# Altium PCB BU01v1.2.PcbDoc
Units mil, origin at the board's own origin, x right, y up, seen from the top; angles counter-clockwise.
Board outline 1015 x 695 mil, 2 copper layers (Top Layer, Bottom Layer); 7 components, 21 nets, 48 pads, 3 vias.
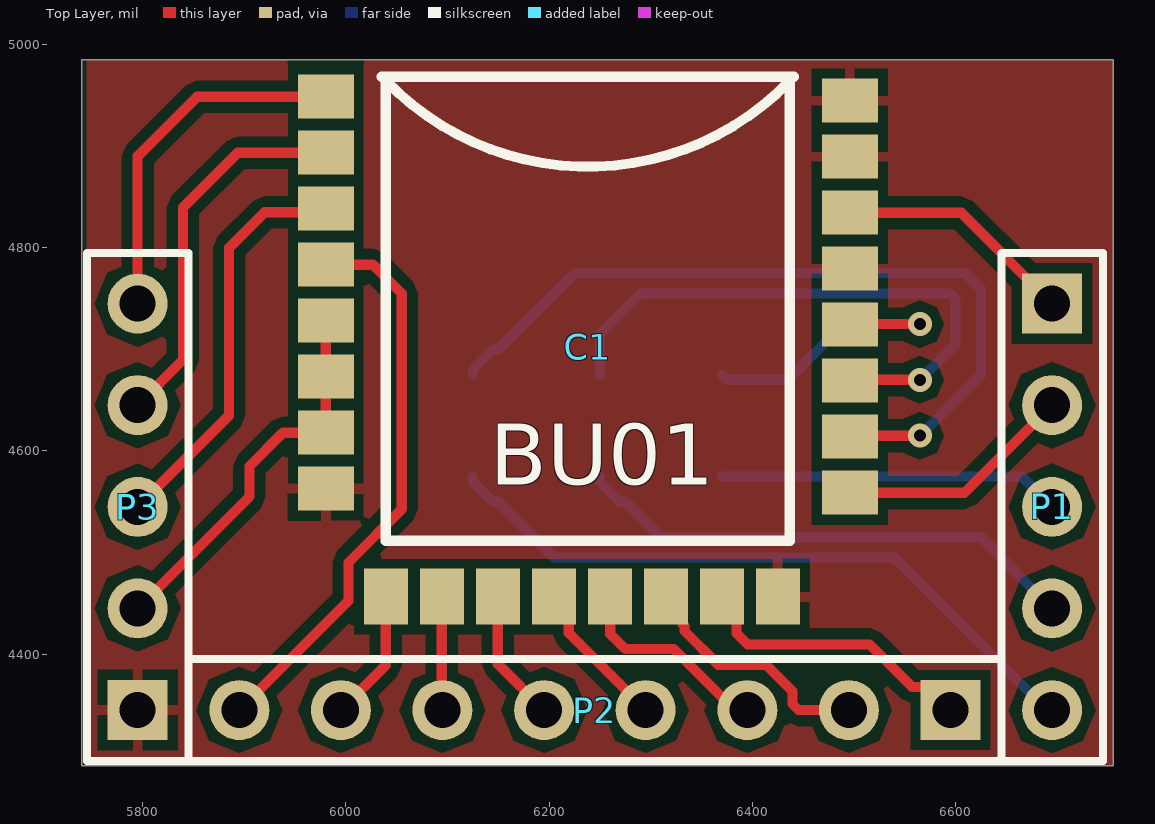
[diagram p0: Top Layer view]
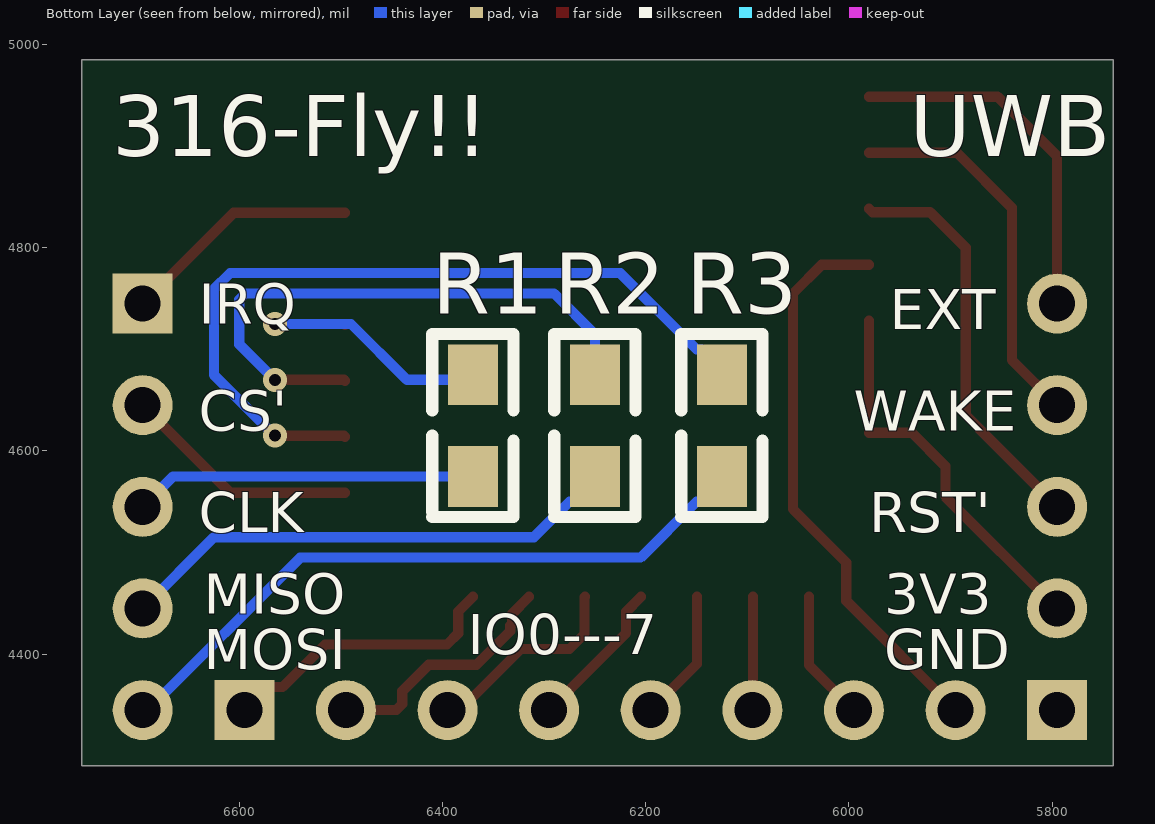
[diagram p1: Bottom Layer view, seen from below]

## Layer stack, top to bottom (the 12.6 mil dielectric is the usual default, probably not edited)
Top Solder: solder mask 0.4, Solder Resist, Dk 3.5
Top Layer: signal copper 1.4
Dielectric 1: dielectric 12.6, FR-4, Dk 4.8
Bottom Layer: signal copper 1.4
Bottom Solder: solder mask 0.4, Solder Resist, Dk 3.5

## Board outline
5740,4290 5740,4985 6755,4985 6755,4290

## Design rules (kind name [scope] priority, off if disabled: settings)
Clearance [All] p1: gap=10 ignorepadtopadclearanceinfootprint=FALSE except(0: Arc-Hole Track-Hole SMDPad-Hole THPad-Hole Via-Hole Fill-Hole Poly-Hole Region-Hole Text-Hole)
ComponentClearance [All] p1 off: gap=10 collisioncheckmode=3 verticalgap=10 showdistances=FALSE
PolygonConnect [All] p1: connectstyle=Relief reliefconductorwidth=10 reliefentries=4 polygonreliefangle="90 Angle" airgapwidth=10
RoutingVias [All] p1: holewidth=28 width=50 viastyle="Through Hole" minholewidth=28 minwidth=50 maxholewidth=28 maxwidth=50
SolderMaskExpansion [All] p1: expansion=4 istentingtop=FALSE
Width [All] p1: maxlimit=10 minlimit=10 preferedwidth=10
29 further rules are at their usual default settings.

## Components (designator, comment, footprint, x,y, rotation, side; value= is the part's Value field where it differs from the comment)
C1 "BU01" BU01 6240,4925 r0 top
P1 "Header 5" HDR1X5 6695,4745 r270 top
P2 "Header 8" HDR1X8 6595,4345 r180 top
P3 "Header 5" HDR1X5 5795,4345 r90 top
R1 "Res Semi" 0805 6370,4675 r270 bottom value=100
R2 "Res Semi" 0805 6250,4675 r270 bottom value=100
R3 "Res Semi" 0805 6125,4675 r270 bottom value=100

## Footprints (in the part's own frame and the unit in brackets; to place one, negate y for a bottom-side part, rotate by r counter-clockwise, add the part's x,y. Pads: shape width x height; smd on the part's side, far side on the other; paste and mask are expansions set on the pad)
0805 [mil]
  rect 60x49.21 smd: 1(0,0) 2(100,0)
  silkscreen extent -40,-40 140,40
BU01 [mm]
  rect 1.4x1.1 smd: 1(-6.6,0.6) 2(-6.6,-0.8) 3(-6.6,-2.2) 4(-6.6,-3.6) 5(-6.6,-5) 6(-6.6,-6.4) 7(-6.6,-7.8) 8(-6.6,-9.2) 17(6.5,-9.3) 18(6.5,-7.9) 19(6.5,-6.5) 20(6.5,-5.1) 21(6.5,-3.7) 22(6.5,-2.3) 23(6.5,-0.9) 24(6.5,0.5)
  rect 1.1x1.4 smd: 9(-5.1,-11.9) 10(-3.7,-11.9) 11(-2.3,-11.9) 12(-0.9,-11.9) 13(0.5,-11.9) 14(1.9,-11.9) 15(3.3,-11.9) 16(4.7,-11.9)
  silkscreen extent -5.2,-10.5 5.1,1.1
HDR1X5 [mm] "Connector; Header; 5 Position"
  rect 1.5x1.5 hole 0.9: 1(0,0)
  round 1.5 hole 0.9: 2(2.54,0) 3(5.08,0) 4(7.62,0) 5(10.16,0)
  silkscreen extent -1.27,-1.27 11.43,1.27
HDR1X8 [mm] "Connector; Header; 8 Position"
  rect 1.5x1.5 hole 0.9: 1(0,0)
  round 1.5 hole 0.9: 2(2.54,0) 3(5.08,0) 4(7.62,0) 5(10.16,0) 6(12.7,0) 7(15.24,0) 8(17.78,0)
  silkscreen extent -1.27,-1.27 19.05,1.27

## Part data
P1 P3: "Header, 5-Pin"
P2: "Header, 8-Pin"
R1 R2 R3: "Semiconductor Resistor"

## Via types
v1: diameter 23.62, hole 11.81, Top Layer to Bottom Layer, 3 vias

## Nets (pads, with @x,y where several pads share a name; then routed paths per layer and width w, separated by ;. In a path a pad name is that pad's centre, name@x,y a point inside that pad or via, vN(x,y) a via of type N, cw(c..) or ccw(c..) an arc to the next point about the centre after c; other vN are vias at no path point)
3V3: C1.5 C1.6 C1.7 P3.2 | length 384.6
  Top Layer w10: P3.2 5905,4555 5905,4585 5937.91,4617.91 C1.7 C1.6 C1.5
CLK: C1.20 R1.1 | length 289.3
  Top Layer w10: C1.20 6496.6,4724.9 v1(6565,4724.9)
  Bottom Layer w10: R1.1 6375,4670 6435,4670 6490,4725 6564.9,4725 v1(6565,4724.9)
CS': C1.17 P1.2 | length 234.8
  Top Layer w10: C1.17 6608.86,4558.86 P1.2
EXTON: C1.1 P3.5 | length 354.4
  Top Layer w10: P3.5 5795,4890 5853.62,4948.62 C1.1
GND: C1.8 C1.16 C1.21 C1.23 C1.24 P3.1
IO0: C1.15 P2.1 | length 283.8
  Top Layer w10: C1.15 6384.43,4441.99 6384.43,4420.57 6395.47,4409.53 6515.47,4409.53 6557.37,4367.63 6572.37,4367.63 P2.1
IO1: C1.14 P2.2 | length 242.7
  Top Layer w10: C1.14 6331.46,4439.84 6331.46,4429.89 6333.27,4428.08 6333.27,4422.72 6366.46,4389.53 6413.44,4389.53 6439.53,4363.44 6439.53,4350.86 6445.39,4345 P2.2
IO2: C1.13 P2.3 | length 202.7
  Top Layer w10: C1.13 6260.21,4455.98 6260.21,4419.79 6275,4405 6322.71,4405 6382.71,4345 P2.3
IO3: C1.12 P2.4 | length 149
  Top Layer w10: C1.12 6219.25,4441.81 6219.25,4420.75 P2.4
IO4: C1.11 P2.5 | length 130.4
  Top Layer w10: C1.11 6149.45,4390.55 P2.5
IO5: C1.10 P2.6 | length 111.8
  Top Layer w10: C1.10 6094.33,4345.67 P2.6
IO6: C1.9 P2.7 | length 129.8
  Top Layer w10: P2.7 6039.21,4389.21 C1.9
IO7: C1.4 P2.8 | length 562.8
  Top Layer w10: P2.8 6002.56,4452.56 6002.56,4490.27 6055,4542.71 6055,4755 6026.73,4783.27 C1.4
IRQ: C1.22 P1.1 | length 236.1
  Top Layer w10: C1.22 6605.55,4834.45 P1.1
MISO: C1.19 R2.1 | length 572
  Top Layer w10: C1.19 6496.81,4670 v1(6565,4670)
  Bottom Layer w10: R2.1 6250,4714.9 6290.1,4755 6594.14,4755 6600,4749.14 6600,4705 v1(6565,4670)
MOSI: C1.18 R3.1 | length 789.7
  Top Layer w10: C1.18 6496.93,4615 v1(6565,4615)
  Bottom Layer w10: R3.1 6125,4680.39 6144.61,4700 6150,4700 6225,4775 6609.14,4775 6625,4759.14 6625,4675 v1(6565,4615)
NetP1_3: P1.3 R1.2 | length 337.4
  Bottom Layer w10: R1.2 6665,4575 P1.3
NetP1_4: P1.4 R2.2 | length 502
  Bottom Layer w10: R2.2 6250,4569.61 6269.61,4550 6275,4550 6310,4515 6625,4515 P1.4
NetP1_5: P1.5 R3.2 | length 668.4
  Bottom Layer w10: R3.2 6125,4569.61 6144.61,4550 6150,4550 6205,4495 6540,4495 6690,4345 P1.5
RST': C1.3 P3.3 | length 403.3
  Top Layer w10: P3.3 5885,4635 5885,4800 5920,4835 5976.77,4835 C1.3
WAKEUP: C1.2 P3.4 | length 376
  Top Layer w10: P3.4 5839.53,4689.53 5839.53,4839.53 5893.5,4893.5 C1.2

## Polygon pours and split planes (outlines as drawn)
GND on Top Layer "GND_L01_P000" (solid, pour order 0): 5745,4985 5745,4290 6755,4290 6755,4985

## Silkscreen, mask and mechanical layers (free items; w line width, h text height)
Bottom Overlay:
  text "UWB" at 5940,4890 h60
  text "316-Fly!!" at 6725,4889.99 h60
  text "IRQ" at 6640,4725 h39.37
  text "EXT" at 5960,4720 h39.37
  text "WAKE" at 5995,4620 h39.37
  text "CS'" at 6640,4620 h39.37
  text "RST'" at 5980,4520 h39.37
  text "CLK" at 6640,4520 h39.37
  text "3V3" at 5965,4440 h39.37
  text "MISO" at 6635,4440 h39.37
  text "IO0---7" at 6375,4400 h39.37
  text "GND" at 5965,4385 h39.37
  text "MOSI" at 6635,4385 h39.37
Mechanical 1:
  the board outline again, w10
